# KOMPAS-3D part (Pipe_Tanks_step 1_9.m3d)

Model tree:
1. X Axis
2. Y Axis
3. Z Axis  (labels: Bend 90 Dn 50; Pipe Dn 50; C:\Program Files\ASCON\KOMPAS-3D V10\Sys\graphic.lyt; Pipe_Tanks_step 1_9.m3d)
     Òîëùèíà ñòåíêè 1 = 1

Referenced files in C:\Documents and Settings\kashirsky\Мои документы\Camtasia Studio\Pipelines3D\Tanks\: Tanks_step 1.a3d, Tanks_step 1.spw
Referenced files in C:\Documents and Settings\kashirsky\Мои документы\Camtasia Studio\Pipelines3D\Tanks\Tanks_step 1_Pipes\: Pipe_Tanks_step 1_9.m3d
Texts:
  Pipe Dn 50
  Steel ASTM A295
  Three Point Plane
  Plane at Angle
  Line and Point Plane
  Axis through Two Vertices
  Axis of Feature
  Axis of Conical Surface
  Axis through Edge
  Trim by Surface
  Trim by Sketch
  Feature with No History
  Intersection Axis of Two Planes
  Two Line Plane
  Line and Face Plane
  Bend by line
  Hole in sheet body
  Cut in sheet body
  Point in CM
  Linear Dimension from Line to Point
  Surface Finish Symbol
  Geometric Tolerance Symbol
  Leader #1
  Leader #2
  Leader #3
  Shape Deviations and Datum
  Node point number
  Mark of coordination axis
  Node point designation
  Mark/Reference designation with leader
  Mark/reference designation on line
  Mark/Reference designation without leader
  Bend 90 Dn 50
  Plane of section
